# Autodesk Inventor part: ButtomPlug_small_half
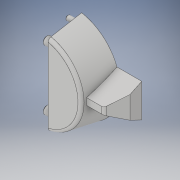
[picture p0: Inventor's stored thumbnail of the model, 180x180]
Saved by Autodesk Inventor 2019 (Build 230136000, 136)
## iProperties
Created: 2021-01
Part Number: ButtomPlug_small_half
Material: Generic
Document SubType Name: Modeling
Designer: Johnny Rex Kancaie
Density: 1 g/cm^3
Appearance: Default
Created: 2021-02
Part Number: ButtomPlug_small_half_3DPrint
Author: Johnny Rex Kancaie
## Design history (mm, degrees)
sketch "Sketch1"
  geometry: C1 r 28 at (0, 0); 1 further point
  constraints: 1 centre point, 1 coincident
  dimensions: "d0" = 56 diameter of C1
workplane "Work Plane1"
sketch "Sketch2"
  geometry: C1 r 24.5 at (0, 0); 1 further point
  constraints: 1 centre point, 1 coincident
  dimensions: "d2" = 49 diameter of C1
loft "Loft1" sketch "Sketch2" dims "d3" = 0, "d4" = 90 deg, "d5" = 0, "d6" = 90 deg
workplane "Work Plane2"
workplane "Work Plane3"
workplane "Work Plane4"
sketch "Sketch12"
  geometry: L1 (-24.5, 20)-(24.5, 20) reference; L2 (28, 0)-(-28, 0) reference; L3 (0, 0)-(0, 17); L4 (0, 0)-(10, 0); L5 (28, 0)-(-28, 0) reference; L6 (0, 17)-(2, 17); L7 (2, 17)-(10, 0); L8 (0, 17)-(-2, 17); L9 (0, 0)-(-10, 0); L10 (-10, 0)-(-2, 17)
  constraints: 14 end point, 3 point on line, 1 parallel, 1 vertical
  dimensions: "d47" = 17 distance of L3.start L3.end; "d48" = 10 distance of L3.start L4.end; "d49" = 2 distance of L3.end L6.end; "d50" = 2 distance of L3.end L8.end; "d51" = 10 distance of L3.start L9.end
  node "Projected Loop9"
extrude "Extrusion9" join sketch "Sketch12" distance "d52" = 17; taper "d53" = 0 deg
workplane "Work Plane5"
sketch "Sketch13"
  geometry: L1 (10, 0)-(2, 17) reference; L2 (10, 0)-(2, 17); L3 (2, 17)-(-2, 17) reference; L4 (2, 17)-(-2, 17); L5 (-2, 17)-(-10, 0) reference; L6 (-2, 17)-(-10, 0); L7 (-10, 0)-(10, 0); L8 (28, 0)-(-28, 0) reference; 1 further point
  constraints: 8 end point, 4 collinear
extrude "Extrusion10" join sketch "Sketch13" distance "d55" = 17; taper "d56" = 0 deg
chamfer "Chamfer1" distance "d57" = 10; stored, may be unused: second distance "d58" = 2, angle "d59" = 30 deg
chamfer "Chamfer2" distance "d60" = 10; stored, may be unused: second distance "d61" = 2, angle "d62" = 30 deg
fillet "Fillet3" dims "d63" = 2
sketch "Sketch14"
  geometry: C1 r 21.5 at (41, -10); 1 further point
  constraints: 1 centre point, 1 coincident
  dimensions: "d64" = 43 diameter of C1
extrude "Extrusion11" cut sketch "Sketch14" distance "d65" = 10; taper "d66" = 0 deg
sketch "Sketch15"
  geometry: L1 (14.847, 0)-(0, 0) reference; L2 (0, -20)-(0, 0) reference; L3 (14.847, -20)-(0, -20) reference; L4 (67.153, -20)-(82, -20) reference; L5 (82, 0)-(82, -20) reference; L6 (67.153, 0)-(82, 0) reference; L7 (14.847, 0)-(0, 0) reference; L8 (0, -20)-(0, 0) reference; L9 (14.847, -20)-(0, -20) reference; L10 (2.969, -16)-(10.969, -16); L11 (10.969, -16)-(10.969, -4); L12 (10.969, -4)-(2.969, -4); L13 (2.969, -4)-(2.969, -16); L14 (2.969, -16)-(10.969, -4); L15 (10.969, -16)-(2.969, -4); L16 (67.153, 0)-(82, 0) reference; L17 (82, 0)-(82, -20) reference; L18 (71.072, -16)-(79.072, -16); L19 (79.072, -16)-(79.072, -4); L20 (79.072, -4)-(71.072, -4); L21 (71.072, -4)-(71.072, -16); L22 (75.072, -12)-(75.072, -8) reference; L23 (71.072, -16)-(79.072, -4); L24 (79.072, -16)-(71.072, -4); C1 r 21.5 at (41, -10) reference; A1 r 28 centre (41, -10) between (67.153, 0) and (14.847, 0) reference; A2 r 28 centre (41, -10) between (14.847, -20) and (67.153, -20) reference; 3 further points
  constraints: 24 end point, 5 midpoint, 4 parallel, 2 horizontal, 2 perpendicular
  dimensions: "d67" = 12 distance of L12.end L10.start; "d68" = 12 distance of L18.end L19.end; "d69" = 8 distance of L19.end L20.end; "d70" = 8 distance of L11.end L12.end
extrude "Extrusion12" cut sketch "Sketch15" distance "d71" = 6; taper "d72" = 0 deg
sketch "Sketch18"
  geometry: C1 r 21.5 at (0, 0) reference; C2 r 2 at (0, 0); 1 further point
  constraints: 1 centre point, 1 coincident
  dimensions: "d77" = 4 diameter of C2
extrude "Extrusion15" cut sketch "Sketch18" extent not by distance; stored distance "d78" = 2; taper "d79" = 0 deg
fillet "Fillet5" dims "d81" = 2
sketch "Sketch20"
  geometry: C1 r 22.5 at (41, -10); 1 further point
  constraints: 1 centre point, 1 coincident
  dimensions: "d82" = 45 diameter of C1
extrude "Extrusion16" cut sketch "Sketch20" distance "d83" = 8; taper "d84" = 0 deg
fillet "Fillet6" dims "d85" = 5
fillet "Fillet7" dims "d86" = 2
workplane "Work Plane6"
sketch "Sketch23"
  geometry: L1 (-30.88, 0)-(30.631, 0); L2 (30.631, 0)-(30.631, 20.981); L3 (30.631, 20.981)-(-30.88, 20.981); L4 (-30.88, 20.981)-(-30.88, 0); 1 further point
  constraints: 8 end point, 2 parallel, 1 horizontal, 1 perpendicular
extrude "Extrusion18" cut sketch "Sketch23" distance "d95" = 49; taper "d96" = 0 deg
sketch "Sketch24"
  geometry: L1 (-20.911, 10)-(20.911, 10) reference; C1 r 2.4 at (18, 15); C2 r 2.4 at (-18, 15); 4 further points
  constraints: 2 centre point, 2 coincident
  dimensions: "d97" = 5 distance from line of L1 point (0, 15); "d98" = 18 distance of point (18, 15) point (0, 15); "d99" = 18 distance of point (0, 15) point (-18, 15); "d100" = 4.8 diameter of C1; "d101" = 4.8 diameter of C2
sketch "Sketch25"
  geometry: L1 (21.937, 0)-(27.55, 0) reference; L2 (21.937, 8)-(21.937, 0) reference; L3 (-27.55, 0)-(-21.937, 0) reference; L4 (-21.937, 0)-(-21.937, 8) reference; C1 r 1.4 at (24.437, 3.5); C2 r 1.4 at (-24.437, 3.5); 3 further points
  constraints: 2 centre point, 2 coincident
  dimensions: "d102" = 3.5 distance from line of point (24.437, 3.5) L1; "d103" = 2.5 distance from line of L2 point (24.437, 3.5); "d104" = 3.5 distance from line of L3 point (-24.437, 3.5); "d105" = 2.5 distance from line of L4 point (-24.437, 3.5); "d106" = 2.8 diameter of C1; "d107" = 2.8 diameter of C2
extrude "Extrusion19" join sketch "Sketch24" distance "d108" = 6; taper "d109" = 0 deg
extrude "Extrusion20" join sketch "Sketch25" distance "d110" = 5; taper "d111" = 0 deg
chamfer "Chamfer3" distance "d112" = 0.5; stored, may be unused: second distance "d113" = 2, angle "d114" = 45 deg
body "Solid1"
node "Projected Loop10"
node "Projected Loop13"
other parameters: "d7" = 22, "d8" = -22, "d46" = 24, "d54" = -24, "d87" = 5
